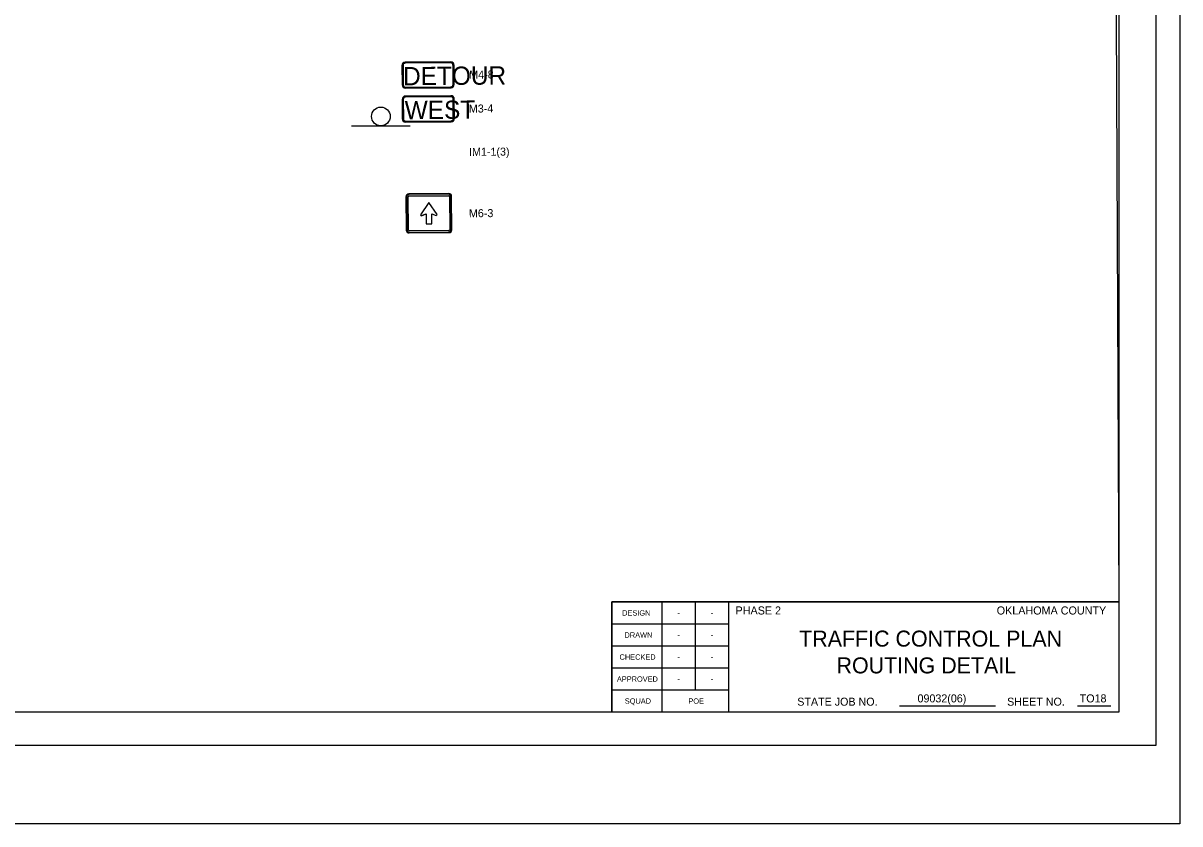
# Model space of a CAD drawing. Extents: x 2162123 to 2216123, y 180770 to 216770.
# Drawn here: x 2190113 to 2216123, y 180770 to 198770 of the extents above; entities that cross this region are included whole.
import ezdxf

# ---------------------------------------------------------------- set-up
doc = ezdxf.new("R2010")
doc.units = 0
for name, color, linetype in [('Default', 7, 'Continuous'), ('PR_Phasing_Detour_1', 7, 'Continuous'), ('SHT_Plot_Shape_Full', 7, 'Continuous'), ('SHT_Plot_Shape_Half', 7, 'Continuous'), ('SHT_Section_Layout_Block', 7, 'Continuous'), ('SHT_Sheet_Border', 7, 'Continuous'), ('SHT_Standard_Sheet_Lines', 7, 'Continuous'), ('SHT_Standard_Sheet_Txt', 7, 'Continuous')]:
    doc.layers.add(name, color=color, linetype=linetype)

# ---------------------------------------------------------------- blocks, each defined once
blk = doc.blocks.new('PRSIGN')
at = {"layer": 'Default'}
blk.add_line((20.04, 6.36), (-20.04, 6.36), dxfattribs=at)
blk.add_circle((0, 0), 6.35, dxfattribs=at)

msp = doc.modelspace()

# ---------------------------------------------------------------- linework, layer by layer
at = {"layer": 'PR_Phasing_Detour_1'}
for p, q in [((2198631, 197820), (2198634, 197380)), ((2198655, 197820), (2198659, 197380)), ((2199729, 197902), (2198704, 197893)), ((2199729, 197877), (2198704, 197869)), ((2199782, 197389), (2199779, 197829)), ((2199807, 197390), (2199803, 197829)), ((2198708, 197332), (2199734, 197340)), ((2198708, 197307), (2199734, 197316)), ((2198635, 197056), (2198638, 196616)), ((2198659, 197056), (2198663, 196617)), ((2199733, 197138), (2198708, 197130)), ((2199733, 197114), (2198708, 197105)), ((2199786, 196626), (2199783, 197065)), ((2199811, 196626), (2199807, 197065)), ((2198712, 196568), (2199738, 196576)), ((2198712, 196544), (2199738, 196552)), ((2198721, 194867), (2198727, 194118)), ((2198740, 194867), (2198746, 194118)), ((2198740, 194867), (2198746, 194118)), ((2198776, 194118), (2198770, 194868)), ((2198776, 194118), (2198770, 194868)), ((2199682, 194940), (2198786, 194933)), ((2199682, 194922), (2198786, 194914)), ((2199682, 194922), (2198786, 194914)), ((2198786, 194884), (2199682, 194891)), ((2198786, 194884), (2199682, 194891)), ((2199698, 194875), (2199704, 194126)), ((2199698, 194875), (2199704, 194126)), ((2199735, 194126), (2199729, 194875)), ((2199735, 194126), (2199729, 194875)), ((2199753, 194126), (2199747, 194875)), ((2199235, 194735), (2199050, 194463)), ((2199425, 194466), (2199235, 194735)), ((2199071, 194442), (2199175, 194485)), ((2199175, 194485), (2199177, 194258)), ((2199302, 194259), (2199300, 194486)), ((2199300, 194486), (2199404, 194445)), ((2199688, 194110), (2198792, 194102)), ((2199688, 194110), (2198792, 194102)), ((2198793, 194072), (2199688, 194079)), ((2198793, 194072), (2199688, 194079)), ((2198793, 194054), (2199689, 194061)), ((2199177, 194258), (2199302, 194259))]:
    msp.add_line(p, q, dxfattribs=at)
for points in [[(2199235, 194734), (2199050, 194462)], [(2199425, 194465), (2199235, 194734)], [(2199071, 194441), (2199175, 194484), (2199177, 194257), (2199302, 194258), (2199300, 194485), (2199404, 194444)]]:
    msp.add_lwpolyline(points, dxfattribs=at)
for centre, radius, start, end in [((2198704, 197820), 73.3, 90.4611, 180.4611), ((2198704, 197820), 48.8, 90.4611, 180.4611), ((2199730, 197828), 73.3, 0.4611, 90.4611), ((2199730, 197828), 48.8, 0.4611, 90.4611), ((2198708, 197381), 73.3, 180.4611, 270.4611), ((2198708, 197381), 48.8, 180.4611, 270.4611), ((2199733, 197389), 73.3, 270.4611, 0.4611), ((2199733, 197389), 48.8, 270.4611, 0.4611), ((2198708, 197057), 73.3, 90.4611, 180.4611), ((2198708, 197057), 48.8, 90.4611, 180.4611), ((2199734, 197065), 73.3, 0.4611, 90.4611), ((2199734, 197065), 48.8, 0.4611, 90.4611), ((2198712, 196617), 73.3, 180.4611, 270.4611), ((2198712, 196617), 48.8, 180.4611, 270.4611), ((2199737, 196625), 48.8, 270.4611, 0.4611), ((2199737, 196625), 73.3, 270.4611, 0.4611), ((2198786, 194868), 64.9, 90.4611, 180.4611), ((2198786, 194868), 46.6, 90.4611, 180.4611), ((2198786, 194868), 46.6, 90.4611, 180.4611), ((2198786, 194868), 16.1, 90.4611, 180.4611), ((2198786, 194868), 16.1, 90.4611, 180.4611), ((2199682, 194875), 64.9, 0.4611, 90.4611), ((2199682, 194875), 46.6, 0.4611, 90.4611), ((2199682, 194875), 46.6, 0.4611, 90.4611), ((2199682, 194875), 16.1, 0.4611, 90.4611), ((2199682, 194875), 16.1, 0.4611, 90.4611), ((2199071, 194463), 20.8, 180.4611, 270.4611), ((2199071, 194462), 20.8, 180.4611, 270.4611), ((2199404, 194466), 20.8, 270.4611, 0.4611), ((2199404, 194465), 20.8, 270.4611, 0.4611), ((2198792, 194119), 64.9, 180.4611, 270.4611), ((2198792, 194119), 46.6, 180.4611, 270.4611), ((2198792, 194119), 46.6, 180.4611, 270.4611), ((2198792, 194119), 16.1, 180.4611, 270.4611), ((2198792, 194119), 16.1, 180.4611, 270.4611), ((2199688, 194126), 46.6, 270.4611, 0.4611), ((2199688, 194126), 16.1, 270.4611, 0.4611), ((2199688, 194126), 46.6, 270.4611, 0.4611), ((2199688, 194126), 16.1, 270.4611, 0.4611), ((2199688, 194126), 64.9, 270.4611, 0.4611)]:
    msp.add_arc(centre, radius, start, end, dxfattribs=at)
at = {"layer": 'SHT_Plot_Shape_Full'}
msp.add_lwpolyline([(2162123, 216770), (2216123, 216770), (2216123, 180770), (2162123, 180770)], close=True, dxfattribs=at)
at = {"layer": 'SHT_Plot_Shape_Half'}
msp.add_lwpolyline([(2164579, 215532), (2215579, 215532), (2215579, 182532), (2164579, 182532)], close=True, dxfattribs=at)
at = {"layer": 'SHT_Section_Layout_Block'}
msp.add_lwpolyline([(2167504, 183282), (2167504, 214782), (2208387, 214782), (2208387, 211973), (2214628, 211973), (2214754, 185757), (2203354, 185757), (2203354, 183282)], close=True, dxfattribs=at)
at = {"layer": 'SHT_Sheet_Border'}
for p, q in [((2203354, 183282), (2203354, 185757)), ((2203354, 185757), (2214754, 185757)), ((2205979, 183282), (2205979, 185758))]:
    msp.add_line(p, q, dxfattribs=at)
msp.add_lwpolyline([(2214754, 183282), (2167504, 183282), (2167504, 214782), (2214754, 214782)], close=True, dxfattribs=at)
at = {"layer": 'SHT_Standard_Sheet_Lines'}
for p, q in [((2204479, 183282), (2204479, 185758)), ((2205229, 183777), (2205229, 185758)), ((2209820, 183426), (2211981, 183426)), ((2213818, 183426), (2214571, 183426))]:
    msp.add_line(p, q, dxfattribs=at)
for points in [[(2205979, 185262), (2203354, 185262)], [(2205979, 184767), (2203354, 184767)], [(2205979, 184272), (2203354, 184272)], [(2205979, 183777), (2203354, 183777)]]:
    msp.add_lwpolyline(points, dxfattribs=at)

# ---------------------------------------------------------------- block references
at = {"layer": 'PR_Phasing_Detour_1', "xscale": 33, "yscale": 33, "rotation": 180}
msp.add_blockref('PRSIGN', (2198157, 196672), dxfattribs=at)

# ---------------------------------------------------------------- texts
at = {"layer": 'PR_Phasing_Detour_1'}
for s, height, p in [('DETOUR', 410.3, (2198658, 197372)), ('M4-8', 180, (2200146, 197522)), ('WEST', 410.3, (2198695, 196609)), ('M3-4', 180, (2200136, 196758)), ('IM1-1(3)', 180, (2200141, 195785)), ('M6-3', 180, (2200138, 194405))]:
    msp.add_text(s, height=height, rotation=0.4611, dxfattribs=at).set_placement(p)
at = {"layer": 'SHT_Standard_Sheet_Txt'}
for s, height, p in [('DESIGN', 120, (2203583, 185451)), ('-', 120, (2204825, 185451)), ('-', 120, (2205575, 185451)), ('DRAWN', 120, (2203636, 184955)), ('-', 120, (2204825, 184955)), ('-', 120, (2205575, 184955)), ('TRAFFIC CONTROL PLAN', 360, (2207563, 184754)), ('CHECKED', 120, (2203524, 184460)), ('-', 120, (2204825, 184460)), ('-', 120, (2205575, 184460)), ('ROUTING DETAIL', 360, (2208403, 184152)), ('APPROVED', 120, (2203465, 183965)), ('-', 120, (2204825, 183965)), ('-', 120, (2205575, 183965)), ('09032(06)', 180, (2210224, 183500)), ('TO18', 180, (2213871, 183500)), ('SQUAD', 120, (2203642, 183470)), ('POE', 120, (2205072, 183470)), ('STATE JOB NO.', 180, (2207520, 183426)), ('SHEET NO. ', 180, (2212239, 183426))]:
    msp.add_text(s, height=height, dxfattribs=at).set_placement(p)
for s, height, p in [('PHASE 2', 181.1, (2206132, 185476)), ('OKLAHOMA COUNTY', 181.06, (2212005, 185476))]:
    msp.add_text(s, height=height, rotation=0, dxfattribs=at).set_placement(p)

doc.saveas('drawing.dxf')
